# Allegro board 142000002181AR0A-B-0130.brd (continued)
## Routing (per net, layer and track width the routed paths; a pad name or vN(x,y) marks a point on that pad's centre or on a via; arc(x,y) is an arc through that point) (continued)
PDU_ISHARE: length 236.8
  TOP w0.127: CONN1.S3 47.27,20.09 53.34,26.16 89.69,26.16 92.14,28.61 108.04,28.61 108.05,28.61 v2(109,28.61) 109,29.1 117.75,37.85 122,37.85 129.62,30.23 v2(171.96,30.23) 181.53,30.23 183.27,31.97 v2(233.43,31.97)
  BOTTOM w0.127: v2(233.43,31.97) 233.17,31.71 233.17,23.37 233.93,22.61 233.93,18.57 CONN4.S3 ; v2(171.96,30.23) v1(171.96,29.21) 171.96,28.96 172.21,28.7 172.21,18.69 CONN3.S3 ; CONN2.S3 109.73,18.5 109.73,20.32 110.22,20.82 110.22,27.39 v2(109,28.61)
PDU_SCL: length 278.6
  TOP w0.127: v2(229.87,28.03) 229.78,28.12 186.06,28.12 179.76,21.82 170.96,21.82 169.21,20.07 168.51,20.07 CONN3.S6 ; CONN1.S6 43.46,25.76 45.38,27.69 89.06,27.69 91.67,30.3 106.4,30.3 106.41,30.31 v2(106.43,30.31)
  BOTTOM w0.127: CONN3.S6 168.4,19.26 168.4,17.98 168.94,17.44 168.94,16.7 168.4,16.16 168.4,14.48 167.64,13.72 106.17,13.72 105.41,14.48 105.41,16.16 104.87,16.7 104.87,17.44 105.41,17.98 105.41,19.26 CONN2.S6 106.43,20.28 v2(106.43,30.31) ; v2(229.87,28.03) 229.87,27.93 230.5,27.29 230.5,19.76 CONN4.S6 230.12,19.38 230.12,18.11 229.36,17.35 229.36,16.79 230.15,16 230.15,15.25 231.24,14.16 248.48,14.16 v1(248.67,13.97) 248.86,14.16 271.54,14.16 R29.1
PDU_SDA: length 280.2
  TOP w0.127: v2(45.06,26.21) 45.16,26.21 46.13,27.18 89.27,27.18 91.81,29.72 v2(107.19,29.72) ; v2(169.08,20.83) 169.25,20.83 170.75,22.32 179.55,22.32 185.85,28.63 230.12,28.63 230.63,28.11 v2(230.63,28.03)
  BOTTOM w0.127: R6.2 45.06,25.96 v2(45.06,26.21) ; R30.2 272.04,14.67 252.41,14.67 v1(252.22,14.86) 252.03,14.67 231.45,14.67 230.66,15.46 230.66,16.11 231.39,16.84 231.39,17.29 230.63,18.05 230.63,18.62 231.39,19.38 231.39,25.35 R2.2 231.45,26.17 231.01,26.6 231.01,27.65 v2(230.63,28.03) ; v2(107.19,29.72) 106.93,29.46 106.93,25.5 R1.2 106.93,25.3 106.93,19.53 106.14,18.73 106.14,17.95 106.64,17.44 106.64,16.7 106.14,16.19 106.14,14.51 106.43,14.22 167.43,14.22 167.79,14.58 167.79,16.08 167.17,16.7 167.17,17.44 167.89,18.17 167.89,18.49 167.13,19.25 167.13,20.32 168.17,21.36 168.17,24.1 R28.2 168.71,21.19 v2(169.08,20.83)
PS1_A0: length 13
  BOTTOM w0.127: v1(45.97,27.18) 45.97,24.64 46.17,24.44 R7.1 46.99,19.81 48.06,18.75 48.06,17.83 47.27,17.04 CONN1.S15
PS1_A1: length 7.8
  BOTTOM w0.127: CONN1.S10 38.61,19.84 R3.2 38.69,24.44 39.37,25.12 v1(39.37,26.92)
PS2_A0: length 12.4
  BOTTOM w0.127: CONN2.S15 109.57,16.93 108.71,17.78 108.71,18.8 109.22,19.3 109.22,20.83 108.97,21.08 R13.1 109.53,24.44 109.73,24.64 109.73,26.74 v1(109.65,26.82)
PS2_A1: length 9.4
  BOTTOM w0.127: CONN2.S10 101.09,20.03 R10.2 102.16,24.44 102.36,24.64 102.36,26.16 101.85,26.67 v1(101.85,27.43)
PS3_A0: length 13.2
  BOTTOM w0.127: v1(171.2,27.43) 170.43,26.67 170.43,24.64 170.63,24.44 R19.1 171.2,20.09 171.36,19.93 171.36,19.21 170.94,18.8 170.94,17.8 171.87,16.88 CONN3.S15
PS3_A1: length 8.1
  BOTTOM w0.127: CONN3.S10 163.32,19.96 R16.2 163.88,24.44 164.08,24.64 v1(164.08,26.92)
PS4_A0: length 13.1
  BOTTOM w0.127: CONN4.S15 234.17,17 234.95,17.78 234.95,18.8 234.44,19.3 234.44,23.37 234.19,23.62 R25.1 233.63,24.44 233.43,24.64 233.43,26.42 233.93,26.92 v1(233.93,27.43)
PS4_A1: length 8.3
  BOTTOM w0.127: v1(225.3,26.92) 225.3,26.16 225.04,25.91 225.04,24.64 225.24,24.44 R22.2 225.81,20.14 CONN4.S10
PSU1_12V_SENSE: length 10.3
  BOTTOM w0.127: v1(50.29,27.18) 51.05,26.42 51.05,25.43 50.07,24.44 R9.2 49.95,24.01 49.95,21.25 49.81,21.1 CONN1.S1
PSU1_ACOK_H: length 273.9
  TOP w0.127: CONN1.S19 42.19,17 41.4,17.78 41.4,18.8 41.91,19.3 41.91,24.93 45.17,28.19 88.84,28.19 91.56,30.91 109.74,30.91 117.43,38.61 122.32,38.61 127.98,32.94 252.48,32.94 265.81,19.61 265.81,18.73 v2(267.53,17.01)
  BOTTOM w0.127: CONN6.27 286.89,9.53 286.76,9.65 284.05,9.65 v1(277.9,15.8) 276.69,17.01 v2(267.53,17.01)
PSU1_EEPROM_WP: length 281.1
  TOP w0.127: CONN1.S18 43.46,18.35 44.49,19.39 44.49,24.68 46.48,26.67 89.48,26.67 91.93,29.12 108.31,29.12 117.54,38.35 122.21,38.35 127.88,32.69 252.03,32.69 v2(263.14,21.58)
  BOTTOM w0.127: CONN6.28 287.81,6.35 291.59,6.35 291.72,6.48 291.72,9.32 290.12,10.92 285.47,10.92 v1(278.79,17.6) 277.9,18.5 266.88,18.5 263.8,21.58 v2(263.14,21.58)
PSU1_PRESENT_L: length 255.4
  TOP w0.127: CONN1.S14 48.54,18.31 55.63,25.4 v2(56.39,25.4) 56.9,25.91 89.79,25.91 92.02,28.14 109.35,28.14 109.47,28.26 109.47,29.21 117.86,37.59 121.9,37.59 129.77,29.72 181.38,29.72 183.16,31.5 251.59,31.5 267.21,15.87 267.21,9.4 270.12,6.48 273.4,6.48 CONN6.8
  BOTTOM w0.127: v2(56.39,25.4) v1(56.39,26.92)
PSU1_PSKILL: length 10.4
  BOTTOM w0.127: v1(41.91,27.43) 42.16,27.43 42.93,26.67 42.93,24.56 42.8,24.44 R5.2 42.16,18.36 CONN1.S7
PSU1_PSON_L: length 296.1
  TOP w0.127: v2(40.39,23.11) 40.39,26.06 42.77,28.45 88.74,28.45 91.46,31.17 109.63,31.17 117.33,38.86 122.42,38.86 128.09,33.2 252.89,33.2 v2(263.08,23)
  BOTTOM w0.127: CONN1.S8 41.15,19.84 R4.2 40.39,23.68 v2(40.39,23.11) ; CONN6.18 282.48,5.33 291.99,5.33 292.63,5.97 292.63,9.59 290.53,11.68 287.38,11.68 280.67,18.39 v1(280.67,18.69) 280.11,19.26 267.38,19.26 263.64,23 v2(263.08,23)
PSU1_PWOK_H: length 267.5
  TOP w0.127: CONN1.S9 39.79,18.49 39.79,25.83 42.66,28.7 88.63,28.7 91.35,31.42 109.53,31.42 117.22,39.12 122.53,39.12 128.19,33.45 250.48,33.45 v2(250.7,33.67) 250.91,33.45 253.3,33.45 268.26,18.49 269.19,18.49 278.29,9.4 279.68,9.4 CONN6.17
  BOTTOM w0.127: v1(250.7,34.54) v2(250.7,33.67)
PSU1_RTN_SENSE: length 8.3
  BOTTOM w0.127: v1(48.01,27.18) 47.75,26.92 47.75,24.64 47.95,24.44 R8.2 48.51,19.63 CONN1.S2
PSU1_SDA: length 9.4
  BOTTOM w0.127: v1(43.94,26.92) 43.94,26.42 43.69,26.16 43.69,24.71 43.96,24.44 R6.1 44.45,23.47 44.73,23.19 CONN1.S5
PSU1_SMB_ALERT_L: length 248
  TOP w0.127: CONN1.S4 46.03,19.61 v2(52.32,25.91) 52.83,26.42 89.58,26.42 92.03,28.87 108.41,28.87 117.65,38.1 122.11,38.1 127.77,32.44 251.01,32.44 267.46,15.98 267.46,11.46 CONN6.1
  BOTTOM w0.127: v1(52.32,26.92) v2(52.32,25.91)
PSU2_12V_SENSE: length 10.6
  BOTTOM w0.127: v1(113.03,27.18) 113.68,26.53 113.68,24.84 113.27,24.44 R15.2 112.01,18.43 CONN2.S1
PSU2_ACOK_H: length 212.3
  TOP w0.127: CONN2.S19 104.49,17.11 105.41,18.03 105.41,18.7 104.87,19.24 104.87,19.98 106.22,21.34 108.2,21.34 111.47,24.6 111.47,29.89 118.41,36.83 121.58,36.83 129.45,28.96 181.7,28.96 183.47,30.73 250.37,30.73 258.79,22.31 259.37,22.31 260.87,20.81 v2(260.87,19.81)
  BOTTOM w0.127: CONN6.29 288.16,9.11 287.37,9.91 284.6,9.91 277.03,17.48 266.46,17.48 264.1,19.84 v1(262.8,19.84) 262.77,19.81 v2(260.87,19.81)
PSU2_EEPROM_WP: length 216.6
  TOP w0.127: CONN2.S18 105.76,18.15 106.71,19.1 106.71,19.33 111.72,24.35 111.72,29.79 118.51,36.58 121.47,36.58 129.35,28.7 181.8,28.7 183.58,30.48 249.9,30.48 259.04,21.34 v2(259.59,21.34)
  BOTTOM w0.127: CONN6.30 288.83,6.6 291.23,6.6 291.36,6.73 291.36,9.32 290.01,10.67 284.92,10.67 277.34,18.24 266.78,18.24 263.91,21.11 262.95,21.11 262.63,21.42 v1(261.11,21.42) 259.68,21.42 v2(259.59,21.34)
PSU2_PRESENT_L: length 196.8
  TOP w0.127: CONN2.S14 110.84,18.38 112.48,20.03 112.48,29.83 118.72,36.07 121.26,36.07 129.03,28.3 v2(129.03,27.94) 182.12,27.94 184.15,29.97 249.29,29.97 266.95,12.31 266.95,8.64 269.49,6.1 274.29,6.1 CONN6.10
  BOTTOM w0.127: v2(129.03,27.94) 129.35,28.26 v1(129.35,28.7)
PSU2_PSKILL: length 9.6
  BOTTOM w0.127: v1(105.66,27.18) 105.66,26.16 105.92,25.91 105.92,25.12 105.24,24.44 R12.2 104.49,23.77 CONN2.S7
PSU2_PSON_L: length 232.3
  TOP w0.127: v2(259.01,22.78) 250.81,30.99 183.37,30.99 181.59,29.21 129.56,29.21 121.68,37.08 118.3,37.08 111.21,30 111.21,25.11 109.22,23.11 v2(103.38,23.11)
  BOTTOM w0.127: v2(259.01,22.78) 259.49,22.3 263.79,22.3 267.09,19 279.19,19 v1(284.73,13.46) 286.77,11.43 290.43,11.43 292.38,9.48 292.38,6.07 291.89,5.59 283.49,5.59 CONN6.20 ; v2(103.38,23.11) 103.38,23.68 R11.2 104.14,20.53 CONN2.S8
PSU2_PWOK_H: length 206.7
  TOP w0.127: CONN2.S9 101.95,23.21 103.63,24.89 109.47,24.89 109.98,25.4 109.98,29.21 118.11,37.34 121.79,37.34 129.66,29.46 181.49,29.46 183.26,31.24 251.22,31.24 265.88,16.58 v2(265.88,16.47)
  BOTTOM w0.127: CONN6.19 281.81,9.32 v1(275.87,15.26) 275.12,16.01 266.34,16.01 v2(265.88,16.47)
PSU2_RTN_SENSE: length 9.1
  BOTTOM w0.127: CONN2.S2 110.74,19.7 R14.2 111.05,24.44 111.25,24.64 111.25,27.94 v1(111,28.19)
PSU2_SDA: length 9.8
  BOTTOM w0.127: CONN2.S5 107.53,18.85 107.53,24.65 107.95,25.07 R1.1 107.95,27.43 v1(107.7,27.69)
PSU2_SMB_ALERT_L: length 194.1
  TOP w0.127: v2(263.31,17.02) 262.6,17.02 249.39,30.23 183.69,30.23 181.91,28.45 129.24,28.45 121.37,36.32 118.62,36.32 112.23,29.93 112.23,24.09 108.3,20.16 CONN2.S4
  BOTTOM w0.127: v2(263.31,17.02) 263.31,16.85 v1(264.41,15.75) 264.99,15.18 274.28,15.18 275.46,13.99 CONN6.9
PSU3_12V_SENSE: length 10.5
  BOTTOM w0.127: v1(176.28,27.43) 176.28,26.67 175.77,26.16 175.77,25.15 175.06,24.44 R21.2 174.24,18.5 CONN3.S1
PSU3_ACOK_H: length 142.6
  TOP w0.127: v2(257.81,20.07) 248.74,29.13 185.49,29.13 181.53,25.17 168.17,25.17 166.88,23.88 166.88,19.66 165.86,18.64 165.86,18.03 166.79,17.11 CONN3.S19
  BOTTOM w0.127: CONN6.31 287.81,10.16 284.71,10.16 277.13,17.73 266.56,17.73 263.7,20.6 259.4,20.6 v1(259.08,20.28) 258.03,20.28 v2(257.81,20.07)
PSU3_EEPROM_WP: length 138.6
  TOP w0.127: CONN3.S18 168.4,17.42 168.4,18.54 171.17,21.31 180.1,21.31 v2(185.71,26.92) 185.97,27.18 249.94,27.18 266.19,10.92 266.19,8.53 269.39,5.33 287.49,5.33 CONN6.32
  BOTTOM w0.127: v1(184.93,27.71) v2(185.71,26.92)
PSU3_PRESENT_L: length 120.9
  TOP w0.127: CONN3.S14 173.14,18.45 175.23,20.55 180.36,20.55 186.48,26.67 248.52,26.67 257.88,17.31 259.01,17.31 v2(265.72,10.6)
  BOTTOM w0.127: v1(264.92,13.46) 265.72,12.66 v2(265.72,10.6) 265.72,10.12 269.74,6.1 275.56,6.1 CONN6.12
PSU3_PSKILL: length 9.8
  BOTTOM w0.127: v1(166.88,27.18) 166.62,26.92 166.62,24.89 166.88,24.64 167.19,24.64 R18.2 166.62,23.68 166.62,18.5 CONN3.S7
PSU3_PSON_L: length 141.2
  TOP w0.127: v2(164.85,25.91) 164.9,25.96 164.9,26.72 165.61,27.43 182.37,27.43 v2(183.13,28.19) 184.66,29.72 249.18,29.72 266.45,12.45 266.45,8.64 269.24,5.84 281.65,5.84 CONN6.22
  BOTTOM w0.127: v2(164.85,25.91) 164.85,25.15 165.35,24.64 165.66,24.64 R17.2 165.86,19.96 CONN3.S8 ; v2(183.13,28.19) 182.63,28.7 v1(182.63,29.21)
PSU3_PWOK_H: length 136.1
  TOP w0.127: v2(259.04,18.74) 259.04,19.5 249.08,29.46 185.15,29.46 182.35,26.67 166.88,26.67 164.25,24.04 CONN3.S9
  BOTTOM w0.127: CONN6.21 283.08,8.86 275.67,16.27 266.95,16.27 265.81,17.41 v1(265.36,17.41) 263.97,18.8 259.1,18.8 v2(259.04,18.74)
PSU3_RTN_SENSE: length 8.3
  BOTTOM w0.127: v1(173.48,27.18) 173.23,27.18 172.72,26.67 172.72,24.87 173.15,24.44 R20.2 173.23,19.7 CONN3.S2
PSU3_SDA: length 8.9
  BOTTOM w0.127: v1(169.16,26.92) 169.62,26.46 R28.1 169.62,24.38 169.67,24.33 169.67,18.69 CONN3.S5
PSU3_SMB_ALERT_L: length 119.4
  TOP w0.127: CONN3.S4 172.04,21.05 180.51,21.05 186.38,26.92 249.43,26.92 v2(258.57,17.78)
  BOTTOM w0.127: CONN6.11 276.73,13.08 274.31,15.51 265.57,15.51 263.59,17.49 v1(262.09,17.49) 261.8,17.78 v2(258.57,17.78)
PSU4_12V_SENSE: length 10.5
  BOTTOM w0.127: CONN4.S1 236.71,20.85 236.47,21.08 R27.2 237.34,24.44 237.74,24.84 v1(237.74,27.69)
PSU4_ACOK_H: length 76
  TOP w0.127: v2(253.34,20.83) 253.08,21.08 251.37,21.08 248.83,23.62 230.38,23.62 229.11,22.35 229.11,19.56 228.09,18.54 228.09,18.03 228.85,17.27 228.85,16.03 CONN4.S19
  BOTTOM w0.127: CONN6.33 290.7,8.97 289.26,10.41 284.81,10.41 277.24,17.99 266.67,17.99 263.8,20.85 255.8,20.85 v1(255.78,20.83) v2(253.34,20.83)
PSU4_EEPROM_WP: length 73.9
  TOP w0.127: CONN4.S18 230.36,18.27 231.65,19.56 231.65,21.59 232.92,22.86 v2(248.92,22.86) 249.23,22.86 253.08,19.01 254.14,19.01 255.11,18.03 256.03,18.03 268.99,5.08 288.51,5.08 CONN6.34
  BOTTOM w0.127: v1(248.92,23.88) v2(248.92,22.86)
PSU4_PRESENT_L: length 53.1
  TOP w0.127: CONN4.S14 235.44,18.52 236.73,19.81 236.73,20.57 237.74,21.59 249.78,21.59 258.16,13.21 v2(259.28,13.21)
  BOTTOM w0.127: v2(259.28,13.21) 259.48,13.41 v1(261.37,13.41) 261.67,13.41 269.34,5.74 276.47,5.74 CONN6.14
PSU4_PSKILL: length 9.9
  BOTTOM w0.127: v1(229.62,27.08) 228.85,26.31 228.85,24.64 229.05,24.44 R24.2 229.09,23.91 CONN4.S7
PSU4_PSON_L: length 93
  TOP w0.127: v2(227.13,24.18) 228.13,25.18 248.37,25.18 v2(251.46,22.1)
  BOTTOM w0.127: v1(227.33,27.43) 227.33,27.27 227.13,27.07 v2(227.13,24.18) 227.38,24.44 R23.2 228.09,19.89 CONN4.S8 ; CONN6.24 285.78,5.84 291.78,5.84 292.08,6.14 292.08,9.42 290.32,11.18 286.03,11.18 v1(280.48,16.72) 278.45,18.75 266.99,18.75 263.69,22.05 252.3,22.05 v1(252.25,22.1) v2(251.46,22.1)
PSU4_PWOK_H: length 69.4
  TOP w0.127: v2(255.52,18.8) 255.52,19.3 253.2,21.63 251.18,21.63 248.17,24.64 230.12,24.64 226.69,21.21 226.69,18.49 CONN4.S9
  BOTTOM w0.127: CONN6.23 284.01,8.54 276.01,16.54 267.04,16.54 264.31,19.27 257.52,19.27 v1(257.3,19.05) 257.05,18.8 v2(255.52,18.8)
PSU4_RTN_SENSE: length 8.5
  BOTTOM w0.127: v1(235.95,26.92) 235.46,26.92 234.95,26.42 234.95,24.56 235.08,24.44 R26.2 235.46,19.63 CONN4.S2
PSU4_SDA: length 9.1
  BOTTOM w0.127: CONN4.S5 231.9,18.62 231.9,22.1 232.36,22.55 R2.1 232.36,26.47 v1(231.9,26.92)
PSU4_SMB_ALERT_L: length 55
  TOP w0.127: CONN4.S4 232.9,21.31 233.68,22.1 249.63,22.1 253.19,18.54 v2(253.49,18.54)
  BOTTOM w0.127: CONN6.13 278,12.32 274.56,15.76 265.93,15.76 263.44,18.25 254.8,18.25 254.76,18.29 v1(254.24,18.29) 253.75,18.29 v2(253.49,18.54)
PSU_VSTB_3V3: length 44.2
  TOP w0.635: CONN1.S11 37.11,19.09 ; CONN1.S11 36.36,18.34 ; CONN1.S11 37.11,17.59 ; 37.11,15.05 CONN1.S23 ; CONN1.S23 37.11,16.55 ; CONN1.S23 36.36,15.8 ; 35.84,18.86 CONN1.S12 ; CONN1.S12 35.84,20.36 ; CONN1.S12 36.58,19.61 ; CONN1.S12 35.09,19.61 ; CONN1.S24 36.58,17.07 ; CONN1.S24 35.84,16.32 ; CONN1.S24 35.84,17.82 ; CONN1.S24 35.09,17.07
  BOTTOM w0.635: CONN3.S11 162.45,18.34 ; CONN3.S11 161.71,19.09 ; CONN3.S11 161.71,17.59 ; CONN3.S11 160.96,18.34 ; CONN2.S12 98.14,20.36 ; CONN2.S12 98.14,18.86 ; CONN2.S12 97.39,19.61 ; CONN2.S12 98.88,19.61 ; 224.01,17.59 CONN4.S11 ; CONN4.S11 223.26,18.34 ; CONN4.S11 224.01,19.09 ; CONN4.S12 222.74,20.36 ; CONN4.S12 223.48,19.61 ; CONN4.S12 221.99,19.61 ; CONN4.S12 222.74,18.86 ; 160.96,15.8 CONN3.S23 ; CONN3.S23 162.45,15.8 ; CONN3.S23 161.71,16.55 ; CONN4.S24 222.74,17.82 ; CONN4.S24 222.74,16.32 ; CONN4.S24 223.48,17.07 ; CONN4.S24 221.99,17.07 ; 98.14,16.32 CONN2.S24 ; CONN2.S24 97.39,17.07 ; CONN2.S24 98.14,17.82 ; CONN2.S24 98.88,17.07 ; CONN2.S11 100.15,18.34 ; CONN2.S11 99.41,17.59 ; CONN2.S11 98.66,18.34 ; CONN2.S11 99.41,19.09 ; CONN3.S12 161.18,19.61 ; CONN3.S12 159.69,19.61 ; CONN3.S12 160.44,20.36 ; CONN3.S12 160.44,18.86 ; 223.26,15.8 CONN4.S23 ; CONN4.S23 224.01,15.05 ; CONN4.S23 224.01,16.55 ; 160.44,16.32 CONN3.S24 ; CONN3.S24 160.44,17.82 ; CONN3.S24 159.69,17.07 ; CONN3.S24 161.18,17.07 ; 99.41,15.05 CONN2.S23 ; CONN2.S23 98.66,15.8 ; CONN2.S23 99.41,16.55 ; CONN2.S23 100.15,15.8
  vias: v1(96.77,27.18) v1(100.08,32.51) v1(160.27,28.7) v1(161.29,33.78) v1(222,29.21) v1(225.3,37.34) v2(96.36,35.97) v2(96.77,33.78) v2(97.12,35.97) v2(97.54,33.78) v2(97.88,35.97) v2(98.3,33.78) v2(98.65,35.97) v2(99.06,33.78) v2(159,37.85) v2(159,36.07) v2(159.77,37.85) v2(159.77,36.07) v2(160.53,37.85) v2(160.53,36.07) v2(161.21,36.07) v2(161.29,37.85) v2(221.23,38.35) v2(221.23,36.58) v2(222,38.35) v2(222,36.58) v2(222.76,38.35) v2(222.76,36.58) v2(223.52,38.35) v2(223.52,36.58)

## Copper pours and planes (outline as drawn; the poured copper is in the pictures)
GND on TOP (solid shape): 392,16 350,16 347.88,15.12 347,13 347,2 346.71,1.29 346,1 1,1 1,3.24 1.63,3.24 1.63,1.63 254.15,1.63 254.55,1.23 258.01,1.23 258.41,1.63 346,1.63 346.26,1.74 346.37,2 346.37,13 347.43,15.57 350,16.63 386.2,16.63 386.61,16.23 389.48,16.23 389.89,16.63 391.36,16.63 391.36,18.27 391.79,18.7 391.79,21.75 391.36,22.18 391.36,53.21 391.78,53.62 391.78,56.37 391.36,56.78 391.36,58.36 389.83,58.36 389.4,58.79 386.36,58.79 385.93,58.36 257.81,58.36 257.36,58.81 254.52,58.81 254.07,58.36 121.73,58.36 121.32,58.78 118.62,58.78 118.21,58.36 7.03,58.36 6.61,58.79 3.22,58.79 2.79,58.36 1.63,58.36 1.63,56.84 1.26,56.47 1.26,56.47 1.23,56.43 1.23,53.68 1.63,53.27 1.63,30.01 1.2,29.58 1.2,26.53 1.63,26.1 1.63,6.74 1,6.74 1,59 392,59
GND on BOTTOM (solid shape): 392,16 350,16 347.88,15.12 347,13 347,2 346.71,1.29 346,1 1,1 1,3.24 1.63,3.24 1.63,1.63 254.15,1.63 254.55,1.23 258.01,1.23 258.41,1.63 346,1.63 346.26,1.74 346.37,2 346.37,13 347.43,15.57 350,16.63 386.2,16.63 386.61,16.23 389.48,16.23 389.89,16.63 391.36,16.63 391.36,18.27 391.79,18.7 391.79,21.75 391.36,22.18 391.36,53.21 391.78,53.62 391.78,56.37 391.36,56.78 391.36,58.36 389.83,58.36 389.4,58.79 386.36,58.79 385.93,58.36 257.81,58.36 257.36,58.81 254.52,58.81 254.07,58.36 121.73,58.36 121.32,58.78 118.62,58.78 118.21,58.36 7.03,58.36 6.61,58.79 3.22,58.79 2.79,58.36 1.63,58.36 1.63,56.84 1.26,56.47 1.26,56.47 1.23,56.43 1.23,53.68 1.63,53.27 1.63,30.01 1.2,29.58 1.2,26.53 1.63,26.1 1.63,6.74 1,6.74 1,59 392,59
GND on V3 (solid shape): 392,16 350,16 347.88,15.12 347,13 347,2 346.71,1.29 346,1 1,1 1,3.24 1.63,3.24 1.63,1.63 254.15,1.63 254.55,1.23 258.01,1.23 258.41,1.63 346,1.63 346.26,1.74 346.37,2 346.37,13 347.43,15.57 350,16.63 386.2,16.63 386.61,16.23 389.48,16.23 389.89,16.63 391.36,16.63 391.36,18.27 391.79,18.7 391.79,21.75 391.36,22.18 391.36,53.21 391.78,53.62 391.78,56.37 391.36,56.78 391.36,58.36 389.83,58.36 389.4,58.79 386.36,58.79 385.93,58.36 257.81,58.36 257.36,58.81 254.52,58.81 254.07,58.36 121.73,58.36 121.32,58.78 118.62,58.78 118.21,58.36 7.03,58.36 6.61,58.79 3.22,58.79 2.79,58.36 1.63,58.36 1.63,56.84 1.26,56.47 1.26,56.47 1.23,56.43 1.23,53.68 1.63,53.27 1.63,30.01 1.2,29.58 1.2,26.53 1.63,26.1 1.63,6.74 1,6.74 1,59 392,59
GND on V5 (solid shape): 392,16 350,16 347.88,15.12 347,13 347,2 346.71,1.29 346,1 1,1 1,3.24 1.63,3.24 1.63,1.63 254.15,1.63 254.55,1.23 258.01,1.23 258.41,1.63 346,1.63 346.26,1.74 346.37,2 346.37,13 347.43,15.57 350,16.63 386.2,16.63 386.61,16.23 389.48,16.23 389.89,16.63 391.36,16.63 391.36,18.27 391.79,18.7 391.79,21.75 391.36,22.18 391.36,53.21 391.78,53.62 391.78,56.37 391.36,56.78 391.36,58.36 389.83,58.36 389.4,58.79 386.36,58.79 385.93,58.36 257.81,58.36 257.36,58.81 254.52,58.81 254.07,58.36 121.73,58.36 121.32,58.78 118.62,58.78 118.21,58.36 7.03,58.36 6.61,58.79 3.22,58.79 2.79,58.36 1.63,58.36 1.63,56.84 1.26,56.47 1.26,56.47 1.23,56.43 1.23,53.68 1.63,53.27 1.63,30.01 1.2,29.58 1.2,26.53 1.63,26.1 1.63,6.74 1,6.74 1,59 392,59
GND on V7 (solid shape): 392,16 350,16 347.88,15.12 347,13 347,2 346.71,1.29 346,1 1,1 1,3.24 1.63,3.24 1.63,1.63 254.15,1.63 254.55,1.23 258.01,1.23 258.41,1.63 346,1.63 346.26,1.74 346.37,2 346.37,13 347.43,15.57 350,16.63 386.2,16.63 386.61,16.23 389.48,16.23 389.89,16.63 391.36,16.63 391.36,18.27 391.79,18.7 391.79,21.75 391.36,22.18 391.36,53.21 391.78,53.62 391.78,56.37 391.36,56.78 391.36,58.36 389.83,58.36 389.4,58.79 386.36,58.79 385.93,58.36 257.81,58.36 257.36,58.81 254.52,58.81 254.07,58.36 121.73,58.36 121.32,58.78 118.62,58.78 118.21,58.36 7.03,58.36 6.61,58.79 3.22,58.79 2.79,58.36 1.63,58.36 1.63,56.84 1.26,56.47 1.26,56.47 1.23,56.43 1.23,53.68 1.63,53.27 1.63,30.01 1.2,29.58 1.2,26.53 1.63,26.1 1.63,6.74 1,6.74 1,59 392,59
GND on V9 (solid shape): 392,16 350,16 347.88,15.12 347,13 347,2 346.71,1.29 346,1 1,1 1,3.24 1.63,3.24 1.63,1.63 254.15,1.63 254.55,1.23 258.01,1.23 258.41,1.63 346,1.63 346.26,1.74 346.37,2 346.37,13 347.43,15.57 350,16.63 386.2,16.63 386.61,16.23 389.48,16.23 389.89,16.63 391.36,16.63 391.36,18.27 391.79,18.7 391.79,21.75 391.36,22.18 391.36,53.21 391.78,53.62 391.78,56.37 391.36,56.78 391.36,58.36 389.83,58.36 389.4,58.79 386.36,58.79 385.93,58.36 257.81,58.36 257.36,58.81 254.52,58.81 254.07,58.36 121.73,58.36 121.32,58.78 118.62,58.78 118.21,58.36 7.03,58.36 6.61,58.79 3.22,58.79 2.79,58.36 1.63,58.36 1.63,56.84 1.26,56.47 1.26,56.47 1.23,56.43 1.23,53.68 1.63,53.27 1.63,30.01 1.2,29.58 1.2,26.53 1.63,26.1 1.63,6.74 1,6.74 1,59 392,59
GND on V11 (solid shape): 392,16 350,16 347.88,15.12 347,13 347,2 346.71,1.29 346,1 1,1 1,3.24 1.63,3.24 1.63,1.63 254.15,1.63 254.55,1.23 258.01,1.23 258.41,1.63 346,1.63 346.26,1.74 346.37,2 346.37,13 347.43,15.57 350,16.63 386.2,16.63 386.61,16.23 389.48,16.23 389.89,16.63 391.36,16.63 391.36,18.27 391.79,18.7 391.79,21.75 391.36,22.18 391.36,53.21 391.78,53.62 391.78,56.37 391.36,56.78 391.36,58.36 389.83,58.36 389.4,58.79 386.36,58.79 385.93,58.36 257.81,58.36 257.36,58.81 254.52,58.81 254.07,58.36 121.73,58.36 121.32,58.78 118.62,58.78 118.21,58.36 7.03,58.36 6.61,58.79 3.22,58.79 2.79,58.36 1.63,58.36 1.63,56.84 1.26,56.47 1.26,56.47 1.23,56.43 1.23,53.68 1.63,53.27 1.63,30.01 1.2,29.58 1.2,26.53 1.63,26.1 1.63,6.74 1,6.74 1,59 392,59
GND on V12 (solid shape): 392,16 350,16 347.88,15.12 347,13 347,2 346.71,1.29 346,1 1,1 1,3.24 1.63,3.24 1.63,1.63 254.15,1.63 254.55,1.23 258.01,1.23 258.41,1.63 346,1.63 346.26,1.74 346.37,2 346.37,13 347.43,15.57 350,16.63 386.2,16.63 386.61,16.23 389.48,16.23 389.89,16.63 391.36,16.63 391.36,18.27 391.79,18.7 391.79,21.75 391.36,22.18 391.36,53.21 391.78,53.62 391.78,56.37 391.36,56.78 391.36,58.36 389.83,58.36 389.4,58.79 386.36,58.79 385.93,58.36 257.81,58.36 257.36,58.81 254.52,58.81 254.07,58.36 121.73,58.36 121.32,58.78 118.62,58.78 118.21,58.36 7.03,58.36 6.61,58.79 3.22,58.79 2.79,58.36 1.63,58.36 1.63,56.84 1.26,56.47 1.26,56.47 1.23,56.43 1.23,53.68 1.63,53.27 1.63,30.01 1.2,29.58 1.2,26.53 1.63,26.1 1.63,6.74 1,6.74 1,59 392,59
GND on V14 (solid shape): 392,16 350,16 347.88,15.12 347,13 347,2 346.71,1.29 346,1 1,1 1,3.24 1.63,3.24 1.63,1.63 254.15,1.63 254.55,1.23 258.01,1.23 258.41,1.63 346,1.63 346.26,1.74 346.37,2 346.37,13 347.43,15.57 350,16.63 386.2,16.63 386.61,16.23 389.48,16.23 389.89,16.63 391.36,16.63 391.36,18.27 391.79,18.7 391.79,21.75 391.36,22.18 391.36,53.21 391.78,53.62 391.78,56.37 391.36,56.78 391.36,58.36 389.83,58.36 389.4,58.79 386.36,58.79 385.93,58.36 257.81,58.36 257.36,58.81 254.52,58.81 254.07,58.36 121.73,58.36 121.32,58.78 118.62,58.78 118.21,58.36 7.03,58.36 6.61,58.79 3.22,58.79 2.79,58.36 1.63,58.36 1.63,56.84 1.26,56.47 1.26,56.47 1.23,56.43 1.23,53.68 1.63,53.27 1.63,30.01 1.2,29.58 1.2,26.53 1.63,26.1 1.63,6.74 1,6.74 1,59 392,59
GND on V16 (solid shape): 392,16 350,16 347.88,15.12 347,13 347,2 346.71,1.29 346,1 1,1 1,3.24 1.63,3.24 1.63,1.63 254.15,1.63 254.55,1.23 258.01,1.23 258.41,1.63 346,1.63 346.26,1.74 346.37,2 346.37,13 347.43,15.57 350,16.63 386.2,16.63 386.61,16.23 389.48,16.23 389.89,16.63 391.36,16.63 391.36,18.27 391.79,18.7 391.79,21.75 391.36,22.18 391.36,53.21 391.78,53.62 391.78,56.37 391.36,56.78 391.36,58.36 389.83,58.36 389.4,58.79 386.36,58.79 385.93,58.36 257.81,58.36 257.36,58.81 254.52,58.81 254.07,58.36 121.73,58.36 121.32,58.78 118.62,58.78 118.21,58.36 7.03,58.36 6.61,58.79 3.22,58.79 2.79,58.36 1.63,58.36 1.63,56.84 1.26,56.47 1.26,56.47 1.23,56.43 1.23,53.68 1.63,53.27 1.63,30.01 1.2,29.58 1.2,26.53 1.63,26.1 1.63,6.74 1,6.74 1,59 392,59
GND on V18 (solid shape): 392,16 350,16 347.88,15.12 347,13 347,2 346.71,1.29 346,1 1,1 1,3.24 1.63,3.24 1.63,1.63 254.15,1.63 254.55,1.23 258.01,1.23 258.41,1.63 346,1.63 346.26,1.74 346.37,2 346.37,13 347.43,15.57 350,16.63 386.2,16.63 386.61,16.23 389.48,16.23 389.89,16.63 391.36,16.63 391.36,18.27 391.79,18.7 391.79,21.75 391.36,22.18 391.36,53.21 391.78,53.62 391.78,56.37 391.36,56.78 391.36,58.36 389.83,58.36 389.4,58.79 386.36,58.79 385.93,58.36 257.81,58.36 257.36,58.81 254.52,58.81 254.07,58.36 121.73,58.36 121.32,58.78 118.62,58.78 118.21,58.36 7.03,58.36 6.61,58.79 3.22,58.79 2.79,58.36 1.63,58.36 1.63,56.84 1.26,56.47 1.26,56.47 1.23,56.43 1.23,53.68 1.63,53.27 1.63,30.01 1.2,29.58 1.2,26.53 1.63,26.1 1.63,6.74 1,6.74 1,59 392,59
GND on V20 (solid shape): 392,16 350,16 347.88,15.12 347,13 347,2 346.71,1.29 346,1 1,1 1,3.24 1.63,3.24 1.63,1.63 254.15,1.63 254.55,1.23 258.01,1.23 258.41,1.63 346,1.63 346.26,1.74 346.37,2 346.37,13 347.43,15.57 350,16.63 386.2,16.63 386.61,16.23 389.48,16.23 389.89,16.63 391.36,16.63 391.36,18.27 391.79,18.7 391.79,21.75 391.36,22.18 391.36,53.21 391.78,53.62 391.78,56.37 391.36,56.78 391.36,58.36 389.83,58.36 389.4,58.79 386.36,58.79 385.93,58.36 257.81,58.36 257.36,58.81 254.52,58.81 254.07,58.36 121.73,58.36 121.32,58.78 118.62,58.78 118.21,58.36 7.03,58.36 6.61,58.79 3.22,58.79 2.79,58.36 1.63,58.36 1.63,56.84 1.26,56.47 1.26,56.47 1.23,56.43 1.23,53.68 1.63,53.27 1.63,30.01 1.2,29.58 1.2,26.53 1.63,26.1 1.63,6.74 1,6.74 1,59 392,59
GND on TOP: 1.52,1.02 1.02,1.52 1.02,58.93 45.21,58.93 45.22,58.92 391.42,58.92 391.93,58.4 391.93,16.63 391.46,16.15 348.84,16.15 346.9,14.22 346.9,2.02 346.09,1.21 291.94,1.21 291.79,1.06 181.79,1.06 181.73,1.13 38.36,1.13 38.34,1.15 32.65,1.15 32.51,1.02 ; 3 cut-outs
GND on BOTTOM: 36.12,1.11 33.03,1.11 33.03,1.14 1.81,1.14 1.07,1.88 1.07,58.14 1.86,58.93 391.22,58.93 391.9,58.26 391.9,16.62 391.42,16.14 348.53,16.14 346.96,14.57 346.96,2.02 346.12,1.18 294.9,1.18 294.88,1.15 223.16,1.15 223.14,1.17 221.42,1.17 221.42,1.14 94.35,1.14 94.32,1.11 ; 21 cut-outs
GND on G2: 1,1 1,59 392,59 392,16 350,16 347.88,15.12 347,13 347,2 346.71,1.29 346,1 ; 10 cut-outs
GND on G4, G6, G8, G10: 1,1 1,59 392,59 392,16 350,16 347.88,15.12 347,13 347,2 346.71,1.29 346,1 ; 8 cut-outs
GND on G13: 1,1 1,59 392,59 392,16 350,16 347.88,15.12 347,13 347,2 346.71,1.29 346,1 ; 8 cut-outs
GND on G15, G17, G19, G21: 1,1 1,59 392,59 392,16 350,16 347.88,15.12 347,13 347,2 346.71,1.29 346,1
GND_1 on TOP (solid shape): outline of 235 points within 1.5,51.5 8.5,58.5
GND_1 on BOTTOM (solid shape): outline of 235 points within 1.5,51.5 8.5,58.5
GND_2 on TOP (solid shape): outline of 235 points within 1.5,24.5 8.5,31.5
GND_2 on BOTTOM (solid shape): outline of 235 points within 1.5,24.5 8.5,31.5
GND_3 on TOP (solid shape): outline of 235 points within 116.5,51.5 123.5,58.5
GND_3 on BOTTOM (solid shape): outline of 235 points within 116.5,51.5 123.5,58.5
GND_4 on TOP (solid shape): outline of 235 points within 319.5,24.5 326.5,31.5
GND_4 on BOTTOM (solid shape): outline of 235 points within 319.5,24.5 326.5,31.5
GND_5 on TOP (solid shape): outline of 235 points within 116.5,24.5 123.5,31.5
GND_5 on BOTTOM (solid shape): outline of 235 points within 116.5,24.5 123.5,31.5
GND_6 on TOP (solid shape): outline of 235 points within 252.5,51.5 259.5,58.5
GND_6 on BOTTOM (solid shape): outline of 235 points within 252.5,51.5 259.5,58.5
GND_7 on TOP (solid shape): outline of 235 points within 252.5,1.5 259.5,8.5
GND_7 on BOTTOM (solid shape): outline of 235 points within 252.5,1.5 259.5,8.5
GND_8 on TOP (solid shape): outline of 235 points within 384.5,16.5 391.5,23.5
GND_8 on BOTTOM (solid shape): outline of 235 points within 384.5,16.5 391.5,23.5
GND_9 on TOP (solid shape): outline of 235 points within 384.5,51.5 391.5,58.5
GND_9 on BOTTOM (solid shape): outline of 235 points within 384.5,51.5 391.5,58.5
PDU_12V on V3, V5, V7, V9, V11, V12, V14, V16, V18, V20: 2.79,57.4 387.86,57.4 390.91,54.36 390.91,20.32 387.86,17.27 348.74,17.27 345.95,14.48 345.95,3.05 344.93,2.03 4.83,2.03 2.54,4.32 2.54,56.13 2.03,56.64
PSU_VSTB_3V3 on TOP: 37.85,14.99 37.59,14.73 35.05,14.73 33.78,16 33.78,30.73 40.39,37.34 104.9,37.34 111.76,44.2 124.46,44.2 128.27,40.39 225.81,40.39 226.57,39.62 226.57,36.58 226.06,36.07 178.56,36.07 178.18,35.69 127.89,35.69 122.94,40.64 115.57,40.64 107.95,33.02 88.39,33.02 88.27,32.89 43.31,32.89 37.85,27.43
PSU_VSTB_3V3 on BOTTOM: 226.06,38.35 226.06,27.94 224.54,26.42 224.54,15.24 224.03,14.73 222,14.73 220.73,16 220.73,38.61 220.98,38.86 225.55,38.86
PSU_VSTB_3V3 on BOTTOM: 96.01,36.32 100.08,36.32 100.58,35.81 100.58,16 99.57,14.99 96.52,14.99 95.76,15.75 95.76,36.07
PSU_VSTB_3V3 on BOTTOM: 162.56,37.85 162.56,15.75 162.05,15.24 159,15.24 158.24,16 158.24,37.85 158.5,38.1 162.31,38.1

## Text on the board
User.Comments: STB V2
Ref Des/Silkscreen Top: P/N:142000002181A REV:0A
User.11: TOP (COMPONENT_SIDE)                       1
User.12: G2 (GND_LAYER_2)                           2
User.13: V5 (VCC_LAYER_5)                             5
User.14: BOT (SOLDER_SIDE)                         14
User.15: SST (SILKSCREEN_TOP)                      23
User.16: SSB (SILKSCREEN_BOTTOM)                   24
User.17: SMT (SOLDER_MASK_TOP)                     25
User.18: SMB (SOLDER_MASK_BOTTOM)                  26
User.19: DRILL(FINISH HOLE SIZE LIST)                  30
User.20: PMT (PASTE_MASK_TOP)                     27
User.21: PMB (PASTE_MASK_BOTTOM)                  28
User.22: DIM (BOARD_DIMENSION)                    29
User.23: V3 (VCC_LAYER_3)                           3
User.24: G4 (SIGNAL_LAYER_4 )                      4
User.25: G6 (GND_LAYER_6)                           6
User.26: V7 (VCC_LAYER_7)                           7
User.27: G8 (GND_LAYER_8)                           8
User.28: V9 (VCC_LAYER_9)                       9
User.29: G10 (GND_LAYER_10)                        10
User.30: V11 (VCC_LAYER_11)                         11
User.31: V12 (VCC_LAYER_12)                            12
User.32: G13 (GND_LAYER_13)                         13
User.34: V14 (VCC_LAYER_14)                            14
User.35: G15 (GND_LAYER_15)                         15
User.36: V16 (VCC_LAYER_16)                            16
User.37: G17 (GND_LAYER_17)                         17
User.38: V18 (VCC_LAYER_18)                            18
User.39: V20 (VCC_LAYER_20)                            20
User.40: G19 (GND_LAYER_19)                         19
User.41: G21 (GND_LAYER_21)                         21
User.45: C6 | C1 | C12 | CONN1 | R1 | C2 | CONN2 | C3 | R28 | CONN3 | R2 | CONN4 | C4 | CONN6 | C13 | CONN5 | C5 | C9 | R3 | R4 | R5 | R6 | R7 | R8 | R9 | R10 | R11 | R12 | R13 | R14 | R15 | C15 | C10 | R16 | R17 | R18 | R19 | R20 | R21 | R22 | R23 | R24 | R25 | R26 | R27 | C18 | C7 | C17 | R29 | R30 | C11 | C16 | C14 | C8 | 2 | 33 | 34 | Excess check:Jul 31 15:27:35 2018 | XY-Check acute:Jul 31 15:29:34 2018 | XY-Check rotation:Jul 31 15:28:08 2018 | XY-Excess check:Jul 31 15:27:35 2018 | XY-bbvia check:Jul 31 15:25:14 2018 | XY-shape pin check:Jul 31 15:27:48 2018 | bbvia check:Jul 31 15:25:14 2018 | check acute:Jul 31 15:29:34 2018 | check rotation:Jul 31 15:28:08 2018 | shape pin check:Jul 31 15:27:48 2018 | FIGURE | SIZE | 12.0 | 24.0 | 30.0 | 40.0 | 43.0 | 67.0 | 261.0 | 90.0 | 118.0 | 125.0 | 138.0 | TOLERANCE | +3.0/-3.0 | +2.0/-2.0 | +3.0/-0.0 | ALL UNITS ARE IN MILS | PLATED | NON-PLATED | QTY | 585 | 96 | 4 | 8 | 3 | 9 | DRILL CHART: TOP to BOTTOM
